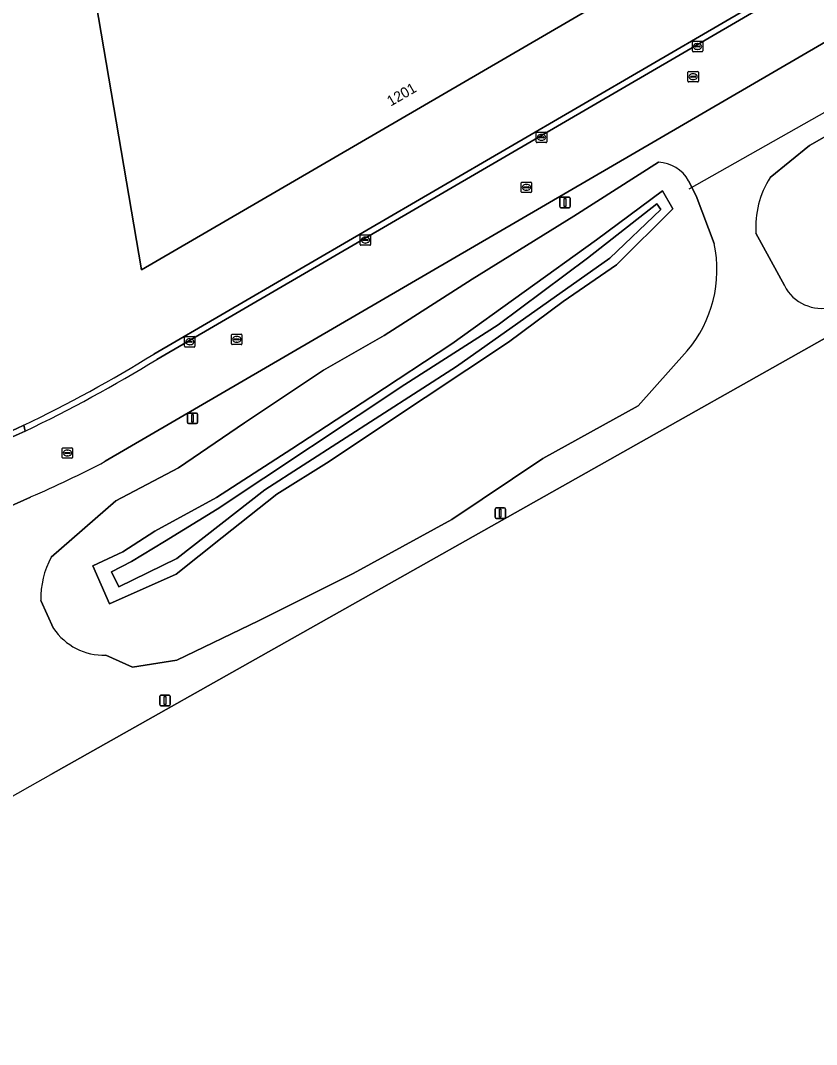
# Model space of a CAD drawing. Extents: x 154324 to 155744, y 382937 to 384188.
# Drawn here: x 154702 to 154778.5, y 382988.6 to 383087 of the extents above; entities that cross this region are included whole.
import ezdxf

# ---------------------------------------------------------------- set-up
doc = ezdxf.new("R2010")
doc.units = 0
for name, color, linetype in [('IMGEO_Berm_groen', 7, 'Continuous'), ('IMGEO_Duiker', 7, 'Continuous'), ('IMGEO_Erf', 7, 'Continuous'), ('IMGEO_Fietspad_gesloten', 7, 'Continuous'), ('IMGEO_Groenvoorziening', 7, 'Continuous'), ('IMGEO_Kolk', 7, 'Continuous'), ('IMGEO_Lichtmast', 7, 'Continuous'), ('IMGEO_Oever', 7, 'Continuous'), ('IMGEO_Pand', 7, 'Continuous'), ('IMGEO_Pand_nummerreeks', 7, 'Continuous'), ('IMGEO_Rijbaan_lokaal_gesloten', 7, 'Continuous'), ('IMGEO_Rioolput', 7, 'Continuous'), ('IMGEO_Waterloop', 7, 'Continuous')]:
    doc.layers.add(name, color=color, linetype=linetype)

msp = doc.modelspace()

# ---------------------------------------------------------------- linework, layer by layer
at = {"layer": 'IMGEO_Berm_groen'}
for points in [[(154991.527, 383204.587), (154991.288, 383204.465), (154988.643, 383202.929), (154972.989, 383194.067), (154922.655, 383165.821), (154870.558, 383136.478), (154807.99, 383101.454), (154807.406, 383100.983), (154799.353, 383096.592), (154796.646, 383095.015), (154788.616, 383090.336), (154781.163, 383085.993), (154710.177, 383044.63)], [(154774.072, 383071.902), (154777.85, 383074.995), (154783.841, 383078.374), (154788.171, 383079.958), (154794.611, 383083.054), (154800.569, 383084.889)], [(154704.991, 383035.409), (154711.178, 383040.819), (154717.203, 383044.008), (154723.572, 383048.333), (154731.149, 383053.399), (154736.971, 383056.739), (154745.442, 383062.14), (154755.204, 383068.201), (154763.357, 383073.382)], [(154658.948, 382988.56), (154668.99, 382994.184), (154672.719, 382996.386), (154679.206, 383000), (154680.529, 383000.746), (154684.215, 383002.824), (154689.553, 383005.833), (154692.996, 383007.774), (154702.968, 383013.395), (154704.954, 383014.514), (154806.83, 383071.943)], [(154766.247, 383071.611), (154766.966, 383070.163), (154768.699, 383065.568)], [(154775.455, 383061.519), (154772.706, 383066.559)], [(154766.114, 383055.237), (154761.412, 383049.964), (154752.245, 383044.915), (154743.48, 383039.05), (154734.016, 383033.845), (154724.899, 383029.278), (154717.04, 383025.524), (154712.786, 383024.833), (154710.229, 383025.985)], [(154703.005, 383041.199), (154652.034, 383018.306), (154642.78, 383014.081)], [(154705.211, 383028.568), (154703.993, 383031.236)]]:
    msp.add_lwpolyline(points, dxfattribs=at)
for centre, radius, start, end in [((154763.179, 383069.848), 3.538, 29.88091, 87.11893), ((154781.758, 383067.091), 9.068, 147.95563, 183.36209), ((154756.953, 383063.018), 12.019, 319.65534, 12.24869), ((154779.02, 383063.34), 4.004, 207.06157, 284.70983), ((154660.302, 383139.674), 107.335, 293.44343, 297.68837), ((154711.959, 383031.537), 7.972, 150.93876, 182.16118), ((154710.059, 383031.821), 5.839, 213.86077, 271.66522)]:
    msp.add_arc(centre, radius, start, end, dxfattribs=at)
at = {"layer": 'IMGEO_Duiker'}
msp.add_lwpolyline([(154808.784, 383094.867), (154766.282, 383070.804)], dxfattribs=at)
at = {"layer": 'IMGEO_Erf'}
for points in [[(154760.793, 383090.488), (154728.376, 383071.611), (154713.674, 383063.037), (154708.101, 383095.793)], [(154714.846, 383054.942), (154776.268, 383090.742)], [(154641.36, 383020.718), (154644.058, 383021.92), (154701.677, 383047.796), (154702.336, 383048.109)]]:
    msp.add_lwpolyline(points, dxfattribs=at)
msp.add_arc((154645.717, 383166.636), 131.356, 295.53316, 301.75384, dxfattribs=at)
at = {"layer": 'IMGEO_Fietspad_gesloten'}
msp.add_lwpolyline([(154806.83, 383071.943), (154806.83, 383071.943), (154704.954, 383014.514), (154806.83, 383071.943)], dxfattribs=at)
at = {"layer": 'IMGEO_Groenvoorziening'}
for points in [[(154800.569, 383084.889), (154794.611, 383083.054), (154788.171, 383079.958), (154783.841, 383078.374), (154777.85, 383074.995), (154774.072, 383071.902)], [(154763.357, 383073.382), (154755.204, 383068.201), (154745.442, 383062.14), (154736.971, 383056.739), (154731.149, 383053.399), (154723.572, 383048.333), (154717.203, 383044.008), (154711.178, 383040.819), (154704.991, 383035.409)], [(154768.699, 383065.568), (154766.966, 383070.163), (154766.247, 383071.611)], [(154772.706, 383066.559), (154775.455, 383061.519)], [(154710.229, 383025.985), (154712.786, 383024.833), (154717.04, 383025.524), (154724.899, 383029.278), (154734.016, 383033.845), (154743.48, 383039.05), (154752.245, 383044.915), (154761.412, 383049.964), (154766.114, 383055.237)], [(154703.993, 383031.236), (154705.211, 383028.568)]]:
    msp.add_lwpolyline(points, dxfattribs=at)
msp.add_lwpolyline([(154764.715, 383068.915), (154759.329, 383063.518), (154754.189, 383059.992), (154748.934, 383056.095), (154736.911, 383048.108), (154731.698, 383044.624), (154726.673, 383041.475), (154721.412, 383037.313), (154716.987, 383033.769), (154710.569, 383030.922), (154708.973, 383034.567), (154711.873, 383035.942), (154714.934, 383037.911), (154720.862, 383041.154), (154728.096, 383045.833), (154735.718, 383050.785), (154743.488, 383055.92), (154757.391, 383065.936), (154763.743, 383070.643)], close=True, dxfattribs=at)
for centre, radius, start, end in [((154763.179, 383069.848), 3.538, 29.88091, 87.11893), ((154781.758, 383067.091), 9.068, 147.95563, 183.36209), ((154756.953, 383063.018), 12.019, 319.65534, 12.24869), ((154779.02, 383063.34), 4.004, 207.06157, 284.70983), ((154711.959, 383031.537), 7.972, 150.93876, 182.16118), ((154710.059, 383031.821), 5.839, 213.86077, 271.66522)]:
    msp.add_arc(centre, radius, start, end, dxfattribs=at)
at = {"layer": 'IMGEO_Kolk'}
for p, q in [((154766.608, 383084.084), (154766.608, 383084.936)), ((154766.683, 383085.01), (154767.535, 383085.01)), ((154767.609, 383084.936), (154767.609, 383084.084)), ((154767.535, 383084.01), (154766.683, 383084.01)), ((154766.867, 383084.504), (154766.867, 383084.516)), ((154767.305, 383084.467), (154766.907, 383084.467)), ((154766.91, 383084.553), (154767.308, 383084.553)), ((154767.119, 383084.23), (154767.094, 383084.23)), ((154767.096, 383084.79), (154767.121, 383084.79)), ((154767.351, 383084.516), (154767.351, 383084.504)), ((154751.609, 383075.348), (154751.609, 383076.2)), ((154751.684, 383076.274), (154752.536, 383076.274)), ((154752.097, 383076.054), (154752.122, 383076.054)), ((154752.61, 383076.2), (154752.61, 383075.348)), ((154752.536, 383075.274), (154751.684, 383075.274)), ((154751.868, 383075.768), (154751.868, 383075.78)), ((154752.306, 383075.731), (154751.908, 383075.731)), ((154751.911, 383075.817), (154752.309, 383075.817)), ((154752.12, 383075.494), (154752.095, 383075.494)), ((154752.352, 383075.78), (154752.352, 383075.768)), ((154734.678, 383065.472), (154734.678, 383066.324)), ((154734.753, 383066.398), (154735.605, 383066.398)), ((154735.166, 383066.178), (154735.191, 383066.178)), ((154735.679, 383066.324), (154735.679, 383065.472)), ((154735.605, 383065.398), (154734.753, 383065.398)), ((154734.937, 383065.892), (154734.937, 383065.904)), ((154735.375, 383065.855), (154734.977, 383065.855)), ((154734.98, 383065.941), (154735.378, 383065.941)), ((154735.189, 383065.618), (154735.164, 383065.618)), ((154735.421, 383065.904), (154735.421, 383065.892)), ((154717.794, 383055.693), (154717.794, 383056.545)), ((154717.869, 383056.619), (154718.721, 383056.619)), ((154718.282, 383056.399), (154718.307, 383056.399)), ((154718.795, 383056.545), (154718.795, 383055.693)), ((154718.721, 383055.619), (154717.869, 383055.619)), ((154718.053, 383056.113), (154718.053, 383056.125)), ((154718.491, 383056.076), (154718.093, 383056.076)), ((154718.096, 383056.162), (154718.494, 383056.162)), ((154718.305, 383055.839), (154718.28, 383055.839)), ((154718.537, 383056.125), (154718.537, 383056.113))]:
    msp.add_line(p, q, dxfattribs=at)
for points in [[(154766.608, 383084.084), (154766.608, 383084.936)], [(154766.683, 383085.01), (154767.535, 383085.01)], [(154767.609, 383084.936), (154767.609, 383084.084)], [(154767.535, 383084.01), (154766.683, 383084.01)], [(154751.609, 383075.348), (154751.609, 383076.2)], [(154751.684, 383076.274), (154752.536, 383076.274)], [(154752.61, 383076.2), (154752.61, 383075.348)], [(154752.536, 383075.274), (154751.684, 383075.274)], [(154734.678, 383065.472), (154734.678, 383066.324)], [(154734.753, 383066.398), (154735.605, 383066.398)], [(154735.679, 383066.324), (154735.679, 383065.472)], [(154735.605, 383065.398), (154734.753, 383065.398)], [(154717.794, 383055.693), (154717.794, 383056.545)], [(154717.869, 383056.619), (154718.721, 383056.619)], [(154718.795, 383056.545), (154718.795, 383055.693)], [(154718.721, 383055.619), (154717.869, 383055.619)]]:
    msp.add_lwpolyline(points, dxfattribs=at)
for centre, radius, start, end in [((154766.685, 383084.934), 0.0765, 91.55205, 178.44795), ((154766.685, 383084.934), 0.0765, 91.55205, 178.44795), ((154767.533, 383084.934), 0.0765, 1.55205, 88.44795), ((154767.533, 383084.934), 0.0765, 1.55205, 88.44795), ((154766.685, 383084.086), 0.0765, 181.55205, 268.44795), ((154766.685, 383084.086), 0.0765, 181.55205, 268.44795), ((154766.907, 383084.513), 0.0403, 85.87752, 175.75265), ((154766.904, 383084.503), 0.0366, 178.93798, 274.71019), ((154767.308, 383084.51), 0.043, 264.86636, 352.45326), ((154767.312, 383084.515), 0.0386, 1.73085, 96.63898), ((154767.533, 383084.086), 0.0765, 271.55205, 358.44795), ((154767.533, 383084.086), 0.0765, 271.55205, 358.44795), ((154751.686, 383076.198), 0.0765, 91.55205, 178.44795), ((154751.686, 383076.198), 0.0765, 91.55205, 178.44795), ((154752.534, 383076.198), 0.0765, 1.55205, 88.44795), ((154752.534, 383076.198), 0.0765, 1.55205, 88.44795), ((154751.686, 383075.35), 0.0765, 181.55205, 268.44795), ((154751.686, 383075.35), 0.0765, 181.55205, 268.44795), ((154751.908, 383075.777), 0.0403, 85.87752, 175.75265), ((154751.905, 383075.767), 0.0366, 178.93798, 274.71019), ((154752.309, 383075.774), 0.043, 264.86636, 352.45326), ((154752.313, 383075.779), 0.0386, 1.73085, 96.63898), ((154752.534, 383075.35), 0.0765, 271.55205, 358.44795), ((154752.534, 383075.35), 0.0765, 271.55205, 358.44795), ((154734.755, 383066.322), 0.0765, 91.55205, 178.44795), ((154734.755, 383066.322), 0.0765, 91.55205, 178.44795), ((154735.603, 383066.322), 0.0765, 1.55205, 88.44795), ((154735.603, 383066.322), 0.0765, 1.55205, 88.44795), ((154734.755, 383065.474), 0.0765, 181.55205, 268.44795), ((154734.755, 383065.474), 0.0765, 181.55205, 268.44795), ((154734.977, 383065.901), 0.0403, 85.87752, 175.75265), ((154734.974, 383065.891), 0.0366, 178.93798, 274.71019), ((154735.378, 383065.898), 0.043, 264.86636, 352.45326), ((154735.382, 383065.903), 0.0386, 1.73085, 96.63898), ((154735.603, 383065.474), 0.0765, 271.55205, 358.44795), ((154735.603, 383065.474), 0.0765, 271.55205, 358.44795), ((154717.871, 383056.543), 0.0765, 91.55205, 178.44795), ((154717.871, 383056.543), 0.0765, 91.55205, 178.44795), ((154718.719, 383056.543), 0.0765, 1.55205, 88.44795), ((154718.719, 383056.543), 0.0765, 1.55205, 88.44795), ((154717.871, 383055.695), 0.0765, 181.55205, 268.44795), ((154717.871, 383055.695), 0.0765, 181.55205, 268.44795), ((154718.093, 383056.122), 0.0403, 85.87752, 175.75265), ((154718.09, 383056.112), 0.0366, 178.93798, 274.71019), ((154718.494, 383056.119), 0.043, 264.86636, 352.45326), ((154718.498, 383056.124), 0.0386, 1.73085, 96.63898), ((154718.719, 383055.695), 0.0765, 271.55205, 358.44795), ((154718.719, 383055.695), 0.0765, 271.55205, 358.44795)]:
    msp.add_arc(centre, radius, start, end, dxfattribs=at)
for centre, major_axis, ratio, start_param, end_param in [((154767.095, 383084.51), (-0.387, 0.002), 0.722429, 4.712389, 7.853982), ((154767.12, 383084.51), (-0.39, 0.002), 0.717154, 1.570796, 4.712389), ((154752.096, 383075.774), (-0.387, 0.002), 0.722429, 4.712389, 7.853982), ((154752.121, 383075.774), (-0.39, 0.002), 0.717154, 1.570796, 4.712389), ((154735.165, 383065.898), (-0.387, 0.002), 0.722429, 4.712389, 7.853982), ((154735.19, 383065.898), (-0.39, 0.002), 0.717154, 1.570796, 4.712389), ((154718.281, 383056.119), (-0.387, 0.002), 0.722429, 4.712389, 7.853982), ((154718.306, 383056.119), (-0.39, 0.002), 0.717154, 1.570796, 4.712389)]:
    msp.add_ellipse(centre, major_axis=major_axis, ratio=ratio, start_param=start_param, end_param=end_param, dxfattribs=at)
at = {"layer": 'IMGEO_Lichtmast'}
for p, q in [((154753.877, 383069.115), (154753.877, 383069.915)), ((154753.877, 383069.915), (154753.877, 383069.115)), ((154753.977, 383070.015), (154754.767, 383070.015)), ((154754.767, 383070.015), (154753.977, 383070.015)), ((154754.867, 383069.915), (154754.867, 383069.115)), ((154754.867, 383069.115), (154754.867, 383069.915)), ((154754.767, 383069.015), (154753.977, 383069.015)), ((154753.977, 383069.015), (154754.767, 383069.015)), ((154718.066, 383048.369), (154718.066, 383049.169)), ((154718.066, 383049.169), (154718.066, 383048.369)), ((154718.166, 383049.269), (154718.956, 383049.269)), ((154718.956, 383049.269), (154718.166, 383049.269)), ((154719.056, 383049.169), (154719.056, 383048.369)), ((154719.056, 383048.369), (154719.056, 383049.169)), ((154718.956, 383048.269), (154718.166, 383048.269)), ((154718.166, 383048.269), (154718.956, 383048.269)), ((154747.643, 383039.245), (154747.643, 383040.045)), ((154747.643, 383040.045), (154747.643, 383039.245)), ((154747.743, 383040.145), (154748.533, 383040.145)), ((154748.533, 383040.145), (154747.743, 383040.145)), ((154748.633, 383040.045), (154748.633, 383039.245)), ((154748.633, 383039.245), (154748.633, 383040.045)), ((154748.533, 383039.145), (154747.743, 383039.145)), ((154747.743, 383039.145), (154748.533, 383039.145)), ((154715.416, 383021.235), (154715.416, 383022.035)), ((154715.416, 383022.035), (154715.416, 383021.235)), ((154715.516, 383022.135), (154716.306, 383022.135)), ((154716.306, 383022.135), (154715.516, 383022.135)), ((154716.406, 383022.035), (154716.406, 383021.235)), ((154716.406, 383021.235), (154716.406, 383022.035)), ((154716.306, 383021.135), (154715.516, 383021.135)), ((154715.516, 383021.135), (154716.306, 383021.135))]:
    msp.add_line(p, q, dxfattribs=at)
for points in [[(154754.297, 383069.89), (154754.447, 383069.89), (154754.447, 383069.14), (154754.297, 383069.14), (154754.297, 383069.89)], [(154718.486, 383049.144), (154718.636, 383049.144), (154718.636, 383048.394), (154718.486, 383048.394), (154718.486, 383049.144)], [(154748.063, 383040.02), (154748.213, 383040.02), (154748.213, 383039.27), (154748.063, 383039.27), (154748.063, 383040.02)], [(154715.836, 383022.01), (154715.986, 383022.01), (154715.986, 383021.26), (154715.836, 383021.26), (154715.836, 383022.01)]]:
    msp.add_lwpolyline(points, dxfattribs=at)
for centre, start, end in [((154753.977, 383069.915), 90, 180), ((154753.977, 383069.915), 90, 180), ((154753.977, 383069.115), 180, 270), ((154753.977, 383069.115), 180, 270), ((154754.767, 383069.915), 0, 90), ((154754.767, 383069.915), 360, 90), ((154754.767, 383069.115), 270, 0), ((154754.767, 383069.115), 270, 0), ((154718.166, 383049.169), 90, 180), ((154718.166, 383049.169), 90, 180), ((154718.956, 383049.169), 0, 90), ((154718.956, 383049.169), 360, 90), ((154718.166, 383048.369), 180, 270), ((154718.166, 383048.369), 180, 270), ((154718.956, 383048.369), 270, 0), ((154718.956, 383048.369), 270, 0), ((154747.743, 383040.045), 90, 180), ((154747.743, 383040.045), 90, 180), ((154748.533, 383040.045), 0, 90), ((154748.533, 383040.045), 360, 90), ((154747.743, 383039.245), 180, 270), ((154747.743, 383039.245), 180, 270), ((154748.533, 383039.245), 270, 0), ((154748.533, 383039.245), 270, 0), ((154715.516, 383022.035), 90, 180), ((154715.516, 383022.035), 90, 180), ((154716.306, 383022.035), 0, 90), ((154716.306, 383022.035), 360, 90), ((154715.516, 383021.235), 180, 270), ((154715.516, 383021.235), 180, 270), ((154716.306, 383021.235), 270, 0), ((154716.306, 383021.235), 270, 0)]:
    msp.add_arc(centre, 0.1, start, end, dxfattribs=at)
at = {"layer": 'IMGEO_Oever'}
for points in [[(154721.412, 383037.313), (154726.673, 383041.475), (154731.698, 383044.624), (154736.911, 383048.108), (154748.934, 383056.095), (154754.189, 383059.992), (154759.329, 383063.518), (154764.715, 383068.915), (154763.743, 383070.643), (154757.391, 383065.936), (154743.488, 383055.92), (154735.718, 383050.785), (154728.096, 383045.833), (154720.862, 383041.154), (154714.934, 383037.911), (154711.873, 383035.942), (154708.973, 383034.567), (154710.569, 383030.922), (154716.987, 383033.769)], [(154763.188, 383069.382), (154763.57, 383068.851), (154758.666, 383064.159), (154743.931, 383053.734), (154725.523, 383041.887), (154717.052, 383035.284), (154711.489, 383032.567), (154710.767, 383034.01), (154712.7, 383034.987), (154715.863, 383036.919), (154720.937, 383040.019), (154738.963, 383052.015), (154747.944, 383057.747), (154756.521, 383064.159)]]:
    msp.add_lwpolyline(points, close=True, dxfattribs=at)
at = {"layer": 'IMGEO_Pand'}
msp.add_lwpolyline([(154749.734, 383170.631), (154766.47, 383173.497), (154761.551, 383202.29), (154680.67, 383188.498), (154696.762, 383093.859), (154708.101, 383095.793), (154713.674, 383063.037), (154728.376, 383071.611), (154760.793, 383090.488), (154758.432, 383104.381), (154777.714, 383107.671), (154772.038, 383140.798), (154755.304, 383137.941), (154750.633, 383165.352), (154750.567, 383165.742)], close=True, dxfattribs=at)
at = {"layer": 'IMGEO_Rijbaan_lokaal_gesloten'}
for points in [[(154710.177, 383044.63), (154781.163, 383085.993), (154788.616, 383090.336), (154796.646, 383095.015), (154799.353, 383096.592), (154807.406, 383100.983), (154807.99, 383101.454), (154870.558, 383136.478), (154922.655, 383165.821), (154972.989, 383194.067), (154988.643, 383202.929), (154991.288, 383204.465), (154991.527, 383204.587), (154994.571, 383206.14), (154995.341, 383206.576), (155027.965, 383225.065), (155055.755, 383240.815)], [(154776.268, 383090.742), (154714.846, 383054.942)], [(154776.571, 383090.255), (154715.149, 383054.429)], [(154715.149, 383054.429), (154776.571, 383090.255)], [(154641.566, 383020.143), (154644.31, 383021.367), (154701.889, 383047.258), (154702.471, 383047.534), (154702.336, 383048.109), (154701.677, 383047.796), (154644.058, 383021.92), (154641.36, 383020.718)], [(154702.471, 383047.534), (154701.889, 383047.258), (154644.31, 383021.367), (154641.566, 383020.143)], [(154702.336, 383048.109), (154702.471, 383047.534)], [(154642.78, 383014.081), (154652.034, 383018.306), (154703.005, 383041.199)]]:
    msp.add_lwpolyline(points, dxfattribs=at)
for centre, radius, start, end in [((154645.717, 383166.636), 131.356, 295.53316, 301.75384), ((154643.796, 383170.525), 136.27, 295.50443, 301.57517), ((154643.796, 383170.525), 136.27, 295.50443, 301.57517), ((154660.302, 383139.674), 107.335, 293.44343, 297.68837)]:
    msp.add_arc(centre, radius, start, end, dxfattribs=at)
at = {"layer": 'IMGEO_Rioolput'}
for p, q in [((154766.181, 383081.177), (154766.181, 383082.029)), ((154766.256, 383082.103), (154767.108, 383082.103)), ((154767.182, 383082.029), (154767.182, 383081.177)), ((154767.108, 383081.103), (154766.256, 383081.103)), ((154766.44, 383081.597), (154766.44, 383081.609)), ((154766.878, 383081.56), (154766.48, 383081.56)), ((154766.483, 383081.646), (154766.881, 383081.646)), ((154766.692, 383081.323), (154766.667, 383081.323)), ((154766.669, 383081.883), (154766.694, 383081.883)), ((154766.924, 383081.609), (154766.924, 383081.597)), ((154750.152, 383070.546), (154750.152, 383071.398)), ((154750.227, 383071.472), (154751.079, 383071.472)), ((154750.64, 383071.252), (154750.665, 383071.252)), ((154751.153, 383071.398), (154751.153, 383070.546)), ((154751.079, 383070.472), (154750.227, 383070.472)), ((154750.411, 383070.966), (154750.411, 383070.978)), ((154750.849, 383070.929), (154750.451, 383070.929)), ((154750.454, 383071.015), (154750.852, 383071.015)), ((154750.663, 383070.692), (154750.638, 383070.692)), ((154750.895, 383070.978), (154750.895, 383070.966)), ((154722.312, 383055.927), (154722.312, 383056.779)), ((154722.387, 383056.853), (154723.239, 383056.853)), ((154722.571, 383056.347), (154722.571, 383056.359)), ((154723.009, 383056.31), (154722.611, 383056.31)), ((154722.614, 383056.396), (154723.012, 383056.396)), ((154722.8, 383056.633), (154722.825, 383056.633)), ((154723.055, 383056.359), (154723.055, 383056.347)), ((154723.313, 383056.779), (154723.313, 383055.927)), ((154723.239, 383055.853), (154722.387, 383055.853)), ((154722.823, 383056.073), (154722.798, 383056.073)), ((154706.035, 383045.001), (154706.035, 383045.853)), ((154706.11, 383045.927), (154706.962, 383045.927)), ((154706.337, 383045.47), (154706.735, 383045.47)), ((154706.523, 383045.707), (154706.548, 383045.707)), ((154707.036, 383045.853), (154707.036, 383045.001)), ((154706.962, 383044.927), (154706.11, 383044.927)), ((154706.294, 383045.421), (154706.294, 383045.433)), ((154706.732, 383045.384), (154706.334, 383045.384)), ((154706.546, 383045.147), (154706.521, 383045.147)), ((154706.778, 383045.433), (154706.778, 383045.421))]:
    msp.add_line(p, q, dxfattribs=at)
for points in [[(154766.181, 383081.177), (154766.181, 383082.029)], [(154766.256, 383082.103), (154767.108, 383082.103)], [(154767.182, 383082.029), (154767.182, 383081.177)], [(154767.108, 383081.103), (154766.256, 383081.103)], [(154750.152, 383070.546), (154750.152, 383071.398)], [(154750.227, 383071.472), (154751.079, 383071.472)], [(154751.153, 383071.398), (154751.153, 383070.546)], [(154751.079, 383070.472), (154750.227, 383070.472)], [(154722.312, 383055.927), (154722.312, 383056.779)], [(154722.387, 383056.853), (154723.239, 383056.853)], [(154723.313, 383056.779), (154723.313, 383055.927)], [(154723.239, 383055.853), (154722.387, 383055.853)], [(154706.035, 383045.001), (154706.035, 383045.853)], [(154706.11, 383045.927), (154706.962, 383045.927)], [(154707.036, 383045.853), (154707.036, 383045.001)], [(154706.962, 383044.927), (154706.11, 383044.927)]]:
    msp.add_lwpolyline(points, dxfattribs=at)
for centre, radius, start, end in [((154766.258, 383082.027), 0.0765, 91.55205, 178.44795), ((154766.258, 383082.027), 0.0765, 91.55205, 178.44795), ((154767.106, 383082.027), 0.0765, 1.55205, 88.44795), ((154767.106, 383082.027), 0.0765, 1.55205, 88.44795), ((154766.258, 383081.179), 0.0765, 181.55205, 268.44795), ((154766.258, 383081.179), 0.0765, 181.55205, 268.44795), ((154766.48, 383081.606), 0.0403, 85.87752, 175.75265), ((154766.477, 383081.596), 0.0366, 178.93798, 274.71019), ((154766.881, 383081.603), 0.043, 264.86636, 352.45326), ((154766.885, 383081.608), 0.0386, 1.73085, 96.63898), ((154767.106, 383081.179), 0.0765, 271.55205, 358.44795), ((154767.106, 383081.179), 0.0765, 271.55205, 358.44795), ((154750.229, 383071.396), 0.0765, 91.55205, 178.44795), ((154750.229, 383071.396), 0.0765, 91.55205, 178.44795), ((154751.077, 383071.396), 0.0765, 1.55205, 88.44795), ((154751.077, 383071.396), 0.0765, 1.55205, 88.44795), ((154750.229, 383070.548), 0.0765, 181.55205, 268.44795), ((154750.229, 383070.548), 0.0765, 181.55205, 268.44795), ((154750.451, 383070.975), 0.0403, 85.87752, 175.75265), ((154750.448, 383070.965), 0.0366, 178.93798, 274.71019), ((154750.852, 383070.972), 0.043, 264.86636, 352.45326), ((154750.856, 383070.977), 0.0386, 1.73085, 96.63898), ((154751.077, 383070.548), 0.0765, 271.55205, 358.44795), ((154751.077, 383070.548), 0.0765, 271.55205, 358.44795), ((154722.389, 383056.777), 0.0765, 91.55205, 178.44795), ((154722.389, 383056.777), 0.0765, 91.55205, 178.44795), ((154722.611, 383056.356), 0.0403, 85.87752, 175.75265), ((154722.608, 383056.346), 0.0366, 178.93798, 274.71019), ((154723.012, 383056.353), 0.043, 264.86636, 352.45326), ((154723.016, 383056.358), 0.0386, 1.73085, 96.63898), ((154723.237, 383056.777), 0.0765, 1.55205, 88.44795), ((154723.237, 383056.777), 0.0765, 1.55205, 88.44795), ((154722.389, 383055.929), 0.0765, 181.55205, 268.44795), ((154722.389, 383055.929), 0.0765, 181.55205, 268.44795), ((154723.237, 383055.929), 0.0765, 271.55205, 358.44795), ((154723.237, 383055.929), 0.0765, 271.55205, 358.44795), ((154706.112, 383045.851), 0.0765, 91.55205, 178.44795), ((154706.112, 383045.851), 0.0765, 91.55205, 178.44795), ((154706.334, 383045.43), 0.0403, 85.87752, 175.75265), ((154706.739, 383045.432), 0.0386, 1.73085, 96.63898), ((154706.96, 383045.851), 0.0765, 1.55205, 88.44795), ((154706.96, 383045.851), 0.0765, 1.55205, 88.44795), ((154706.112, 383045.003), 0.0765, 181.55205, 268.44795), ((154706.112, 383045.003), 0.0765, 181.55205, 268.44795), ((154706.331, 383045.42), 0.0366, 178.93798, 274.71019), ((154706.735, 383045.427), 0.043, 264.86636, 352.45326), ((154706.96, 383045.003), 0.0765, 271.55205, 358.44795), ((154706.96, 383045.003), 0.0765, 271.55205, 358.44795)]:
    msp.add_arc(centre, radius, start, end, dxfattribs=at)
for centre, major_axis, ratio, start_param, end_param in [((154766.668, 383081.603), (-0.387, 0.002), 0.722429, 4.712389, 7.853982), ((154766.693, 383081.603), (-0.39, 0.002), 0.717154, 1.570796, 4.712389), ((154750.639, 383070.972), (-0.387, 0.002), 0.722429, 4.712389, 7.853982), ((154750.664, 383070.972), (-0.39, 0.002), 0.717154, 1.570796, 4.712389), ((154722.799, 383056.353), (-0.387, 0.002), 0.722429, 4.712389, 7.853982), ((154722.824, 383056.353), (-0.39, 0.002), 0.717154, 1.570796, 4.712389), ((154706.522, 383045.427), (-0.387, 0.002), 0.722429, 4.712389, 7.853982), ((154706.547, 383045.427), (-0.39, 0.002), 0.717154, 1.570796, 4.712389)]:
    msp.add_ellipse(centre, major_axis=major_axis, ratio=ratio, start_param=start_param, end_param=end_param, dxfattribs=at)
at = {"layer": 'IMGEO_Waterloop'}
msp.add_lwpolyline([(154763.188, 383069.382), (154756.521, 383064.159), (154747.944, 383057.747), (154738.963, 383052.015), (154720.937, 383040.019), (154715.863, 383036.919), (154712.7, 383034.987), (154710.767, 383034.01), (154711.489, 383032.567), (154717.052, 383035.284), (154725.523, 383041.887), (154743.931, 383053.734), (154758.666, 383064.159), (154763.57, 383068.851)], close=True, dxfattribs=at)

# ---------------------------------------------------------------- texts
at = {"layer": 'IMGEO_Pand_nummerreeks'}
msp.add_text('1201', height=1, rotation=30.21206, dxfattribs=at).set_placement((154737.616, 383078.727))

doc.saveas('drawing.dxf')
